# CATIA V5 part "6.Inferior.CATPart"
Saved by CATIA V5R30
Part number: 6.Inferior
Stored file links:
  C:\Users\valen\Desktop\Estandar CubeSat - Programa AVES-20220531T050024Z-001\Estandar CubeSat - Programa AVES\3D - MODELS\CATIA\6.Inferior.CATPart

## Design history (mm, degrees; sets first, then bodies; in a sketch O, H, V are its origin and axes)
Body1 "Solid1" (main body)
  Solid1: solid without history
